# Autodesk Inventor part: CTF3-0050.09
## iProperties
Shininess: 64.0
Length Units: 11269
Angle Units: 11279
Time Units: 11290
Mass Units: 11283
Length Display Precision: 3
Angle Display Precision: 2
Compacted: True
Part Number: CTF3-0050.09
Document SubType Name: Modeling
Created: 2003-12
Designer: Lollo
Density: 0.0
Volumn: 0.0
Area: 0.0
PropertySet Name: Model Information
Control State: 0
Master: False
Checked Out: False
Author: Lollo
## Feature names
1. Rivoluzione1 [Revolution]
2. Specchio1 [Mirror]
3. Serie rettangolare1 [Rectangular Pattern]
